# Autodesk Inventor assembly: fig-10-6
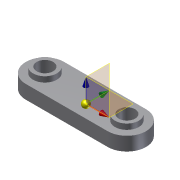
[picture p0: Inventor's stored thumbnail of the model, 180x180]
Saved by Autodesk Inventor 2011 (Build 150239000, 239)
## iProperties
Created: 2010-08
Part Number: fig-10-6
Document SubType Name: Assembly
Designer: CADSoft
Author: CADSoft
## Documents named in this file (2)
- C:\Users\CADSoft\Desktop\part files\c10-inv-2011-prt\fig-10-6.iam
- C:\Users\CADSoft\Desktop\part files\c10-inv-2011-prt\Part6.ipt
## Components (1 placed, 1 different names)
1. Part6:1
